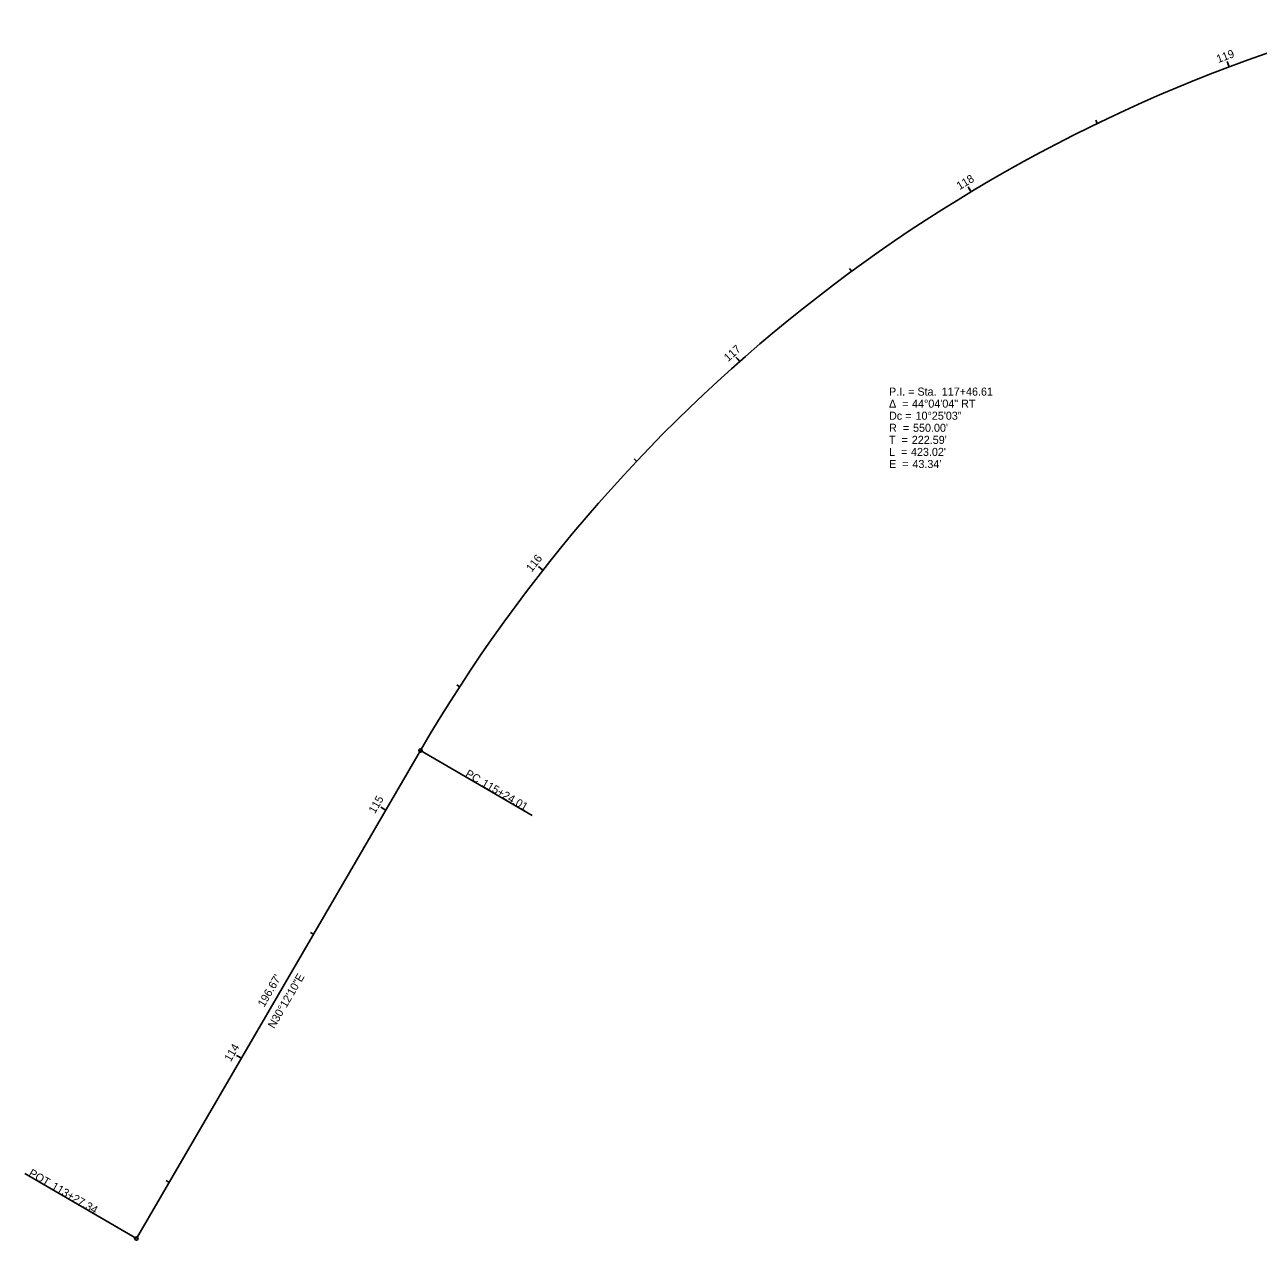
# Model space of a CAD drawing. Extents: x 2325404 to 2326256, y 693508 to 694271.
# Drawn here: x 2325404.1 to 2325833.6, y 693507.6 to 693930.9 of the extents above; entities that cross this region are included whole.
import ezdxf

# ---------------------------------------------------------------- set-up
doc = ezdxf.new("R2010")
doc.units = 0
for name, color, linetype in [('GE_P_Alignment_100_Bearings', 7, 'Continuous'), ('GE_P_Alignment_100_Cardinal_Points', 7, 'Continuous'), ('GE_P_Alignment_100_Distances', 7, 'Continuous'), ('GE_X_Alignment', 7, 'Continuous'), ('GE_X_Alignment_1000_Curve_Data', 7, 'Continuous'), ('GE_X_Alignment_1000_Stations', 7, 'Continuous'), ('GE_X_Alignment_100_Curve_Data', 7, 'Continuous'), ('GE_X_Alignment_100_Stations', 7, 'Continuous'), ('GE_X_Alignment_500_Curve_Data', 7, 'Continuous'), ('GE_X_Alignment_500_Stations', 7, 'Continuous')]:
    doc.layers.add(name, color=color, linetype=linetype)

msp = doc.modelspace()

# ---------------------------------------------------------------- linework, layer by layer
at = {"layer": 'GE_P_Alignment_100_Cardinal_Points'}
for p, q in [((2325823.5, 693916.22), (2325822.8, 693918.09)), ((2325823.5, 693916.22), (2325823.08, 693917.34)), ((2325777.57, 693896.5), (2325777.05, 693897.58)), ((2325733.62, 693872.69), (2325732.59, 693874.41)), ((2325733.62, 693872.69), (2325733, 693873.72)), ((2325692.02, 693845), (2325691.31, 693845.96)), ((2325653.1, 693813.64), (2325651.77, 693815.13)), ((2325617.18, 693778.87), (2325616.31, 693779.69)), ((2325584.57, 693740.99), (2325583, 693742.23)), ((2325584.57, 693740.99), (2325583.63, 693741.73)), ((2325555.54, 693700.31), (2325554.53, 693700.96)), ((2325529.86, 693657.41), (2325528.13, 693658.42)), ((2325479.55, 693570.99), (2325477.82, 693571.99))]:
    msp.add_line(p, q, dxfattribs=at)
at = {"layer": 'GE_X_Alignment'}
msp.add_line((2325443, 693508.19), (2325541.94, 693678.16), dxfattribs=at)
msp.add_arc((2326017.28, 693401.48), 550, 105.7296, 149.7973, dxfattribs=at)
at = {"layer": 'GE_X_Alignment_1000_Stations'}
for p, q in [((2325541.94, 693678.16), (2325580.83, 693655.53)), ((2325529.86, 693657.41), (2325528.82, 693658.01)), ((2325443, 693508.19), (2325404.11, 693530.83))]:
    msp.add_line(p, q, dxfattribs=at)
for centre in [(2325541.94, 693678.16), (2325443, 693508.19)]:
    msp.add_circle(centre, 0.6, dxfattribs=at)
at = {"layer": 'GE_X_Alignment_100_Stations'}
for p, q in [((2325541.94, 693678.16), (2325580.83, 693655.53)), ((2325529.86, 693657.41), (2325528.13, 693658.42)), ((2325504.71, 693614.2), (2325503.67, 693614.8)), ((2325443, 693508.19), (2325404.11, 693530.83)), ((2325454.4, 693527.77), (2325453.36, 693528.38))]:
    msp.add_line(p, q, dxfattribs=at)
for centre in [(2325541.94, 693678.16), (2325443, 693508.19)]:
    msp.add_circle(centre, 0.6, dxfattribs=at)
at = {"layer": 'GE_X_Alignment_500_Stations'}
for p, q in [((2325653.1, 693813.64), (2325652.3, 693814.53)), ((2325541.94, 693678.16), (2325580.83, 693655.53)), ((2325479.55, 693570.99), (2325478.52, 693571.59)), ((2325443, 693508.19), (2325404.11, 693530.83))]:
    msp.add_line(p, q, dxfattribs=at)
for centre in [(2325541.94, 693678.16), (2325443, 693508.19)]:
    msp.add_circle(centre, 0.6, dxfattribs=at)

# ---------------------------------------------------------------- texts
at = {"layer": 'GE_P_Alignment_100_Bearings'}
msp.add_text('N30°12\'10"E', height=2.8, rotation=59.7973, dxfattribs=at).set_placement((2325490.99, 693581.1))
at = {"layer": 'GE_P_Alignment_100_Cardinal_Points'}
for s, rotation, p in [('119', 20.6293, (2325819.7, 693917.5)), ('118', 31.0467, (2325729.63, 693873.26)), ('117', 41.4641, (2325649.05, 693813.39)), ('116', 51.8815, (2325580.63, 693740.09)), ('115', 59.7973, (2325526.07, 693655.97)), ('114', 59.7973, (2325475.84, 693569.57))]:
    msp.add_text(s, height=2.8, rotation=rotation, dxfattribs=at).set_placement(p)
at = {"layer": 'GE_P_Alignment_100_Distances'}
msp.add_text("196.67'", height=2.8, rotation=59.7973, dxfattribs=at).set_placement((2325487.48, 693588.58))
at = {"layer": 'GE_X_Alignment_1000_Curve_Data'}
for s, p in [('P.I. = Sta. ', (2325705.06, 693801.72)), ('117+46.61', (2325723.43, 693801.72)), ('Δ  = ', (2325705.06, 693797.52)), ('44°04\'04" RT', (2325713.08, 693797.52)), ('Dc = ', (2325705.06, 693793.32)), ('10°25\'03"', (2325714.3, 693793.32)), ('R  = ', (2325705.06, 693789.12)), ("550.00'", (2325713.42, 693789.12)), ('T  = ', (2325705.06, 693784.92)), ("222.59'", (2325712.99, 693784.92)), ('L  = ', (2325705.06, 693780.72)), ("423.02'", (2325712.7, 693780.72)), ('E  = ', (2325705.06, 693776.52)), ("43.34'", (2325713.21, 693776.52))]:
    msp.add_text(s, height=2.8, dxfattribs=at).set_placement(p)
at = {"layer": 'GE_X_Alignment_1000_Stations'}
for s, p in [('PC', (2325557.29, 693669.28)), ('115+24.01', (2325562.93, 693666)), ('POT', (2325405.26, 693530.21)), ('113+27.34', (2325413.15, 693525.62))]:
    msp.add_text(s, height=2.8, rotation=329.7973, dxfattribs=at).set_placement(p)
at = {"layer": 'GE_X_Alignment_100_Curve_Data'}
for s, p in [('P.I. = Sta. ', (2325705.06, 693801.72)), ('117+46.61', (2325723.43, 693801.72)), ('Δ  = ', (2325705.06, 693797.52)), ('44°04\'04" RT', (2325713.08, 693797.52)), ('Dc = ', (2325705.06, 693793.32)), ('10°25\'03"', (2325714.3, 693793.32)), ('R  = ', (2325705.06, 693789.12)), ("550.00'", (2325713.42, 693789.12)), ('T  = ', (2325705.06, 693784.92)), ("222.59'", (2325712.99, 693784.92)), ('L  = ', (2325705.06, 693780.72)), ("423.02'", (2325712.7, 693780.72)), ('E  = ', (2325705.06, 693776.52)), ("43.34'", (2325713.21, 693776.52))]:
    msp.add_text(s, height=2.8, dxfattribs=at).set_placement(p)
at = {"layer": 'GE_X_Alignment_100_Stations'}
for s, rotation, p in [('PC', 329.7973, (2325557.29, 693669.28)), ('115+24.01', 329.7973, (2325562.93, 693666)), ('115', 59.7973, (2325526.07, 693655.97)), ("196.67'", 59.7973, (2325487.48, 693588.58)), ('N30°12\'10"E', 59.7973, (2325490.99, 693581.1)), ('POT', 329.7973, (2325405.26, 693530.21)), ('113+27.34', 329.7973, (2325413.15, 693525.62))]:
    msp.add_text(s, height=2.8, rotation=rotation, dxfattribs=at).set_placement(p)
at = {"layer": 'GE_X_Alignment_500_Curve_Data'}
for s, p in [('P.I. = Sta. ', (2325705.06, 693801.72)), ('117+46.61', (2325723.43, 693801.72)), ('Δ  = ', (2325705.06, 693797.52)), ('44°04\'04" RT', (2325713.08, 693797.52)), ('Dc = ', (2325705.06, 693793.32)), ('10°25\'03"', (2325714.3, 693793.32)), ('R  = ', (2325705.06, 693789.12)), ("550.00'", (2325713.42, 693789.12)), ('T  = ', (2325705.06, 693784.92)), ("222.59'", (2325712.99, 693784.92)), ('L  = ', (2325705.06, 693780.72)), ("423.02'", (2325712.7, 693780.72)), ('E  = ', (2325705.06, 693776.52)), ("43.34'", (2325713.21, 693776.52))]:
    msp.add_text(s, height=2.8, dxfattribs=at).set_placement(p)
at = {"layer": 'GE_X_Alignment_500_Stations'}
for s, rotation, p in [('PC', 329.7973, (2325557.29, 693669.28)), ('115+24.01', 329.7973, (2325562.93, 693666)), ("196.67'", 59.7973, (2325487.48, 693588.58)), ('N30°12\'10"E', 59.7973, (2325490.99, 693581.1)), ('POT', 329.7973, (2325405.26, 693530.21)), ('113+27.34', 329.7973, (2325413.15, 693525.62))]:
    msp.add_text(s, height=2.8, rotation=rotation, dxfattribs=at).set_placement(p)

doc.saveas('drawing.dxf')
